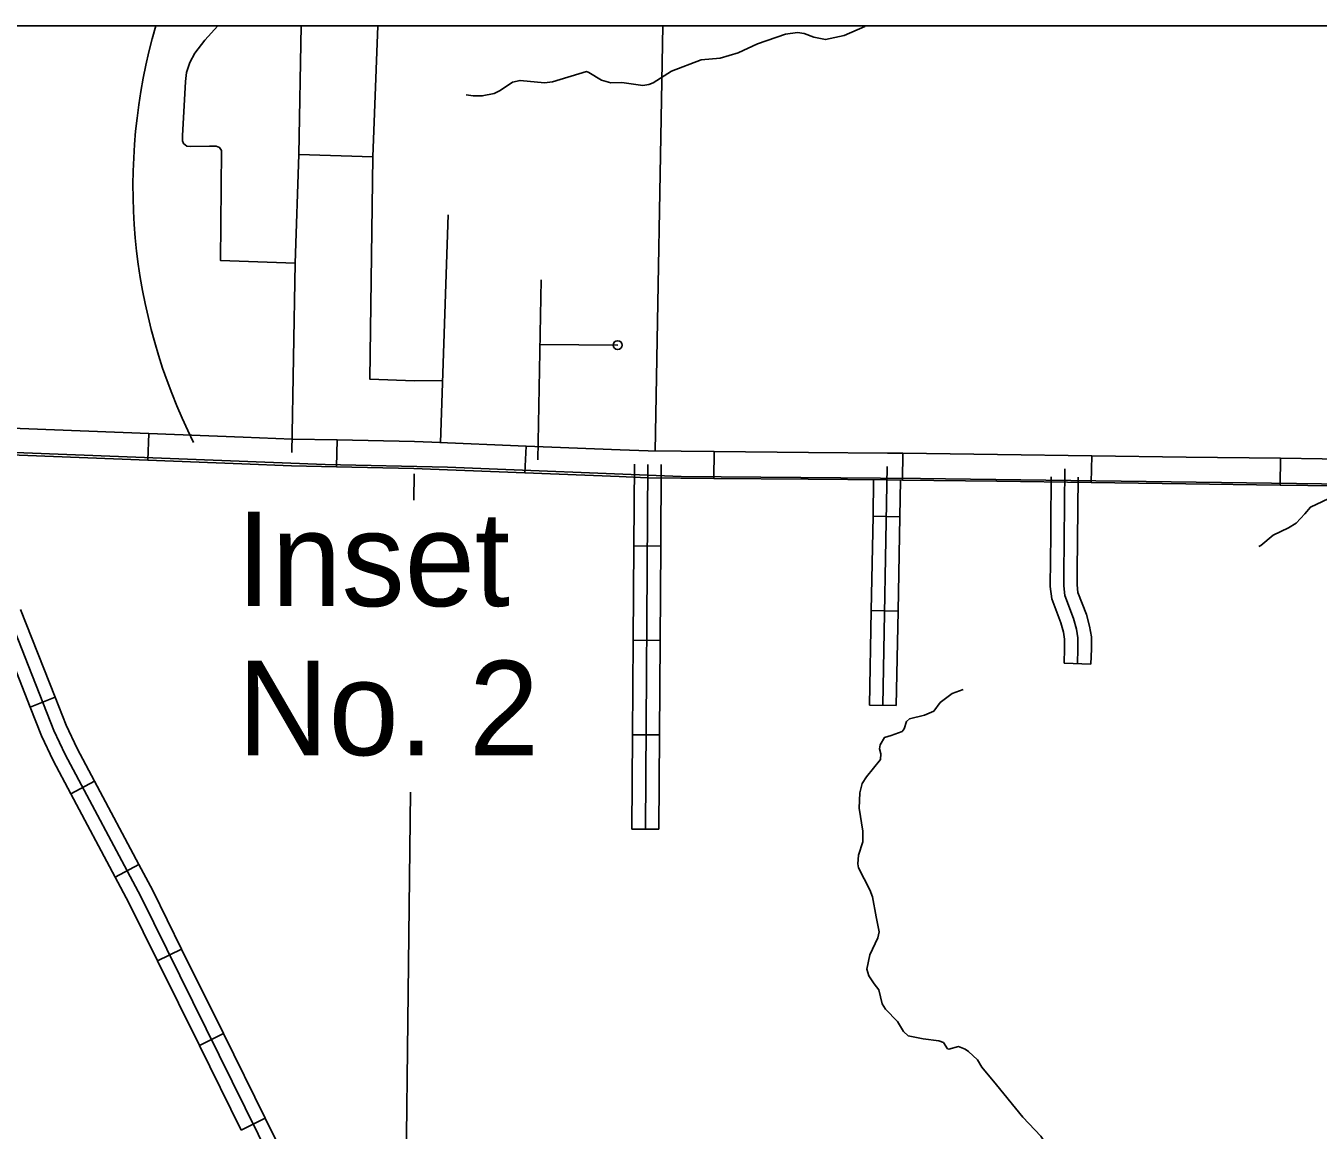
# Model space of a CAD drawing. Extents: x 1370567 to 1373900, y 377514 to 379648.
# Drawn here: x 1372406 to 1372612.6, y 378566.7 to 378743.2 of the extents above; entities that cross this region are included whole.
import ezdxf

# ---------------------------------------------------------------- set-up
doc = ezdxf.new("R2010")
doc.units = 0
doc.layers.add('Default', color=7, linetype='Continuous')
doc.layers.add('Survey Symbols', color=7, linetype='Continuous')

msp = doc.modelspace()

# ---------------------------------------------------------------- linework, layer by layer
at = {"layer": 'Default'}
for p, q in [((1372425.52, 378673.78), (1372425.69, 378678.07)), ((1372455.8, 378677.02), (1372455.71, 378672.74)), ((1372485.82, 378671.76), (1372486, 378676.05)), ((1372516.08, 378675.17), (1372516.05, 378670.88)), ((1372546.21, 378670.61), (1372546.26, 378674.89)), ((1372561.35, 378674.69), (1372561.35, 378674.69)), ((1372576.43, 378674.49), (1372576.37, 378670.21)), ((1372606.54, 378669.81), (1372606.6, 378674.1)), ((1372545.75, 378664.75), (1372541.47, 378664.82)), ((1372507.54, 378660.06), (1372503.25, 378660.09)), ((1372545.48, 378649.66), (1372541.19, 378649.74)), ((1372507.43, 378644.98), (1372503.15, 378645.01)), ((1372576.3, 378641.19), (1372572.02, 378641.33)), ((1372406.71, 378634.34), (1372410.7, 378635.91)), ((1372545.2, 378634.58), (1372540.92, 378634.66)), ((1372507.33, 378629.89), (1372503.04, 378629.92)), ((1372413.22, 378620.48), (1372417, 378622.49)), ((1372507.22, 378614.81), (1372502.94, 378614.84)), ((1372420.31, 378607.16), (1372424.1, 378609.18)), ((1372427.1, 378593.76), (1372430.94, 378595.66)), ((1372433.78, 378580.24), (1372437.62, 378582.14)), ((1372440.47, 378566.72), (1372444.31, 378568.62))]:
    msp.add_line(p, q, dxfattribs=at)
for points in [[(1372437.33, 378723.3), (1372437, 378723.74), (1372436.45, 378723.98), (1372435.37, 378723.98), (1372432.33, 378723.9), (1372431.79, 378723.98), (1372431.25, 378724.37), (1372431.09, 378724.83), (1372431.09, 378725.61), (1372431.56, 378734.32), (1372431.71, 378735.72), (1372432.26, 378737.35), (1372433.03, 378738.83), (1372434.67, 378740.93), (1372436.72, 378743.2)], [(1372449.7, 378722.63), (1372450.07, 378743.2)], [(1372462.28, 378743.2), (1372461.52, 378722.25)], [(1372476.41, 378732.17), (1372477.55, 378732), (1372479.01, 378731.99), (1372480.9, 378732.38), (1372481.84, 378732.84), (1372483.82, 378734.18), (1372485.05, 378734.49), (1372488.93, 378734.1), (1372490.24, 378734.24), (1372495.68, 378735.88), (1372496.02, 378735.76), (1372498.07, 378734.5), (1372499.53, 378734.09), (1372501.32, 378734.17), (1372504.66, 378733.67), (1372505.61, 378733.81), (1372506.35, 378734.1), (1372509.27, 378735.95), (1372514.02, 378737.76), (1372517.02, 378738.03), (1372519.94, 378738.91), (1372523, 378740.3), (1372527.49, 378741.89), (1372529.38, 378742.14), (1372530.49, 378741.99), (1372532.03, 378741.38), (1372533.86, 378741.01), (1372536.86, 378741.65), (1372540.15, 378743.07), (1372540.29, 378743.2)], [(1372507.89, 378743.2), (1372506.64, 378675.25)], [(1372437.33, 378723.3), (1372437.15, 378705.72), (1372449.08, 378705.28)], [(1372437.33, 378723.3), (1372437.15, 378705.72), (1372449.08, 378705.28)], [(1372448.57, 378675.03), (1372449.08, 378705.28), (1372449.7, 378722.63), (1372461.52, 378722.25), (1372461.04, 378686.71), (1372468.15, 378686.48), (1372472.6, 378686.5)], [(1372472.32, 378676.6), (1372473.56, 378713)], [(1372488.4, 378702.6), (1372487.86, 378673.84)], [(1372488.21, 378692.25), (1372500.65, 378692.17)], [(1372410.61, 378678.65), (1372395.54, 378679.24)], [(1372425.69, 378678.07), (1372410.61, 378678.65)], [(1372425.69, 378678.07), (1372440.76, 378677.48)], [(1372392.11, 378677.23), (1372410.49, 378630.59), (1372412.3, 378626.75), (1372424.41, 378604.04), (1372464.02, 378523.91), (1372466.31, 378518.55), (1372469.72, 378512.56)], [(1372440.76, 378677.48), (1372448.63, 378677.17), (1372455.8, 378677.02)], [(1372470.92, 378676.65), (1372468.19, 378676.76), (1372455.8, 378677.02)], [(1372486, 378676.05), (1372470.92, 378676.65)], [(1372486, 378676.05), (1372501.07, 378675.44)], [(1372410.44, 378674.37), (1372395.37, 378674.96)], [(1372625.23, 378669.83), (1372549.05, 378670.84), (1372510.78, 378671.17), (1372473.43, 378672.67), (1372453.87, 378673.08), (1372397.41, 378675.28)], [(1372425.52, 378673.78), (1372410.44, 378674.37)], [(1372501.07, 378675.44), (1372505.53, 378675.26), (1372516.08, 378675.17)], [(1372531.17, 378675.04), (1372516.08, 378675.17)], [(1372546.26, 378674.89), (1372543.78, 378674.93), (1372531.17, 378675.04)], [(1372546.26, 378674.89), (1372561.35, 378674.69)], [(1372561.35, 378674.69), (1372576.43, 378674.49)], [(1372591.52, 378674.29), (1372576.43, 378674.49)], [(1372606.6, 378674.1), (1372591.52, 378674.29)], [(1372606.6, 378674.1), (1372619.96, 378673.92), (1372621.69, 378673.89)], [(1372440.59, 378673.2), (1372425.52, 378673.78)], [(1372455.71, 378672.74), (1372448.5, 378672.89), (1372440.59, 378673.2)], [(1372470.75, 378672.37), (1372468.06, 378672.48), (1372455.71, 378672.74)], [(1372485.82, 378671.76), (1372470.75, 378672.37)], [(1372503.25, 378660.09), (1372503.34, 378673.13)], [(1372505.08, 378614.82), (1372505.48, 378673.12)], [(1372507.54, 378660.06), (1372507.63, 378673.1)], [(1372543.06, 378634.62), (1372543.75, 378672.78)], [(1372574.16, 378641.26), (1372574.24, 378643.67), (1372574.24, 378645.38), (1372574, 378646.78), (1372573.54, 378648.47), (1372572.14, 378652.15), (1372571.96, 378653.72), (1372571.96, 378655.47), (1372572.13, 378672.41)], [(1372618.41, 378671.81), (1372617.72, 378671.27), (1372616.4, 378669.21), (1372615.23, 378668.1), (1372611.39, 378666.29), (1372610.5, 378665.23), (1372609.13, 378663.72), (1372607.92, 378662.95), (1372605.43, 378661.82), (1372603.46, 378660.17), (1372603.14, 378660)], [(1372468.1, 378671.63), (1372468.05, 378667.42)], [(1372500.9, 378671.16), (1372485.82, 378671.76)], [(1372516.05, 378670.88), (1372505.43, 378670.97), (1372500.9, 378671.16)], [(1372531.13, 378670.75), (1372516.05, 378670.88)], [(1372546.21, 378670.61), (1372543.73, 378670.64), (1372531.13, 378670.75)], [(1372541.47, 378664.82), (1372541.57, 378670.66)], [(1372545.75, 378664.75), (1372545.86, 378670.61)], [(1372561.29, 378670.41), (1372546.21, 378670.61)], [(1372576.37, 378670.21), (1372561.29, 378670.41)], [(1372569.83, 378656.02), (1372569.98, 378671.1)], [(1372574.11, 378655.97), (1372574.26, 378671.06)], [(1372591.46, 378670.01), (1372576.37, 378670.21)], [(1372606.54, 378669.81), (1372591.46, 378670.01)], [(1372621.62, 378669.61), (1372619.89, 378669.63), (1372606.54, 378669.81)], [(1372541.19, 378649.74), (1372541.47, 378664.82)], [(1372545.48, 378649.66), (1372545.75, 378664.75)], [(1372503.15, 378645.01), (1372503.25, 378660.09)], [(1372507.43, 378644.98), (1372507.54, 378660.06)], [(1372572.02, 378641.33), (1372572.09, 378643.7), (1372572.09, 378645.2), (1372571.91, 378646.32), (1372571.5, 378647.8), (1372570.04, 378651.64), (1372569.82, 378653.6), (1372569.82, 378655.48), (1372569.83, 378656.02)], [(1372576.3, 378641.19), (1372576.38, 378643.64), (1372576.38, 378645.56), (1372576.1, 378647.24), (1372575.58, 378649.14), (1372574.24, 378652.65), (1372574.11, 378653.84), (1372574.11, 378655.46), (1372574.11, 378655.97)], [(1372405.16, 378649.94), (1372410.7, 378635.91)], [(1372540.92, 378634.66), (1372541.19, 378649.74)], [(1372545.2, 378634.58), (1372545.48, 378649.66)], [(1372401.18, 378648.37), (1372406.71, 378634.34)], [(1372503.04, 378629.92), (1372503.15, 378645.01)], [(1372507.33, 378629.89), (1372507.43, 378644.98)], [(1372555.87, 378637.15), (1372554.12, 378636.5), (1372552.23, 378635.07), (1372551.17, 378633.7), (1372549.68, 378633.05), (1372547.31, 378632.46), (1372546.85, 378632), (1372546.44, 378630.83), (1372546.13, 378630.43), (1372544.38, 378629.78), (1372543.33, 378629.47), (1372542.61, 378628.27), (1372542.52, 378627.64), (1372542.74, 378626.84), (1372542.66, 378625.93), (1372540.42, 378623.16), (1372539.76, 378622.14), (1372539.35, 378620.62), (1372539.25, 378618.16), (1372539.87, 378614.5), (1372539.83, 378612.82), (1372539.17, 378610.67), (1372539.05, 378609.27), (1372539.13, 378608.64), (1372540.97, 378605.12), (1372541.4, 378604), (1372541.99, 378600.83), (1372542.43, 378598.43), (1372542.26, 378597.43), (1372540.99, 378594.71), (1372540.47, 378592.46), (1372540.83, 378591.37), (1372541.66, 378590.08), (1372542.42, 378589.16), (1372542.96, 378586.9), (1372543.47, 378586.04), (1372545.4, 378584.06), (1372546.34, 378582.46), (1372547.11, 378581.8), (1372549.48, 378581.33), (1372551.99, 378581.01), (1372552.73, 378580.75), (1372553.36, 378579.72)], [(1372410.7, 378635.91), (1372412.46, 378631.44), (1372414.22, 378627.72), (1372417, 378622.49)], [(1372406.71, 378634.34), (1372408.52, 378629.74), (1372410.39, 378625.79), (1372413.22, 378620.48)], [(1372502.94, 378614.84), (1372503.04, 378629.92)], [(1372507.22, 378614.81), (1372507.33, 378629.89)], [(1372417, 378622.49), (1372424.1, 378609.18)], [(1372413.22, 378620.48), (1372420.31, 378607.16)], [(1372467.52, 378620.72), (1372466.43, 378524.64)], [(1372424.1, 378609.18), (1372426.31, 378605.02), (1372430.94, 378595.66)], [(1372420.31, 378607.16), (1372422.5, 378603.06), (1372427.1, 378593.76)], [(1372430.94, 378595.66), (1372437.62, 378582.14)], [(1372427.1, 378593.76), (1372433.78, 378580.24)], [(1372437.62, 378582.14), (1372444.31, 378568.62)], [(1372433.78, 378580.24), (1372440.47, 378566.72)], [(1372553.36, 378579.72), (1372553.58, 378579.66), (1372555.13, 378580.08), (1372556.21, 378579.65), (1372556.75, 378579.28), (1372558.15, 378577.93), (1372558.88, 378576.78), (1372561.19, 378573.94), (1372565.45, 378568.78), (1372568.32, 378565.77), (1372568.89, 378564.85), (1372568.96, 378561.57)], [(1372444.31, 378568.62), (1372450.99, 378555.09)]]:
    msp.add_lwpolyline(points, dxfattribs=at)
msp.add_circle((1372500.65, 378692.17), 0.714, dxfattribs=at)
msp.add_arc((1372514.52, 378717.57), 91.36, 163.7093, 206.6443, dxfattribs=at)
at = {"layer": 'Survey Symbols'}
msp.add_lwpolyline([(1371518.13, 378743.2), (1373025.55, 378743.2), (1373025.55, 377817.56), (1371518.13, 377817.56)], close=True, dxfattribs=at)
msp.add_lwpolyline([(1371518.13, 378743.2), (1373025.55, 378743.2), (1373025.55, 377817.56), (1371518.13, 377817.56)], close=True, dxfattribs=at)
msp.add_lwpolyline([(1371518.13, 378743.2), (1373025.55, 378743.2), (1373025.55, 377817.56), (1371518.13, 377817.56)], close=True, dxfattribs=at)

# ---------------------------------------------------------------- texts
at = {"layer": 'Default'}
for s, p in [('Inset', (1372439.69, 378650.46)), ('No. 2', (1372439.87, 378626.64))]:
    msp.add_text(s, height=15.086, dxfattribs=at).set_placement(p)

doc.saveas('drawing.dxf')
